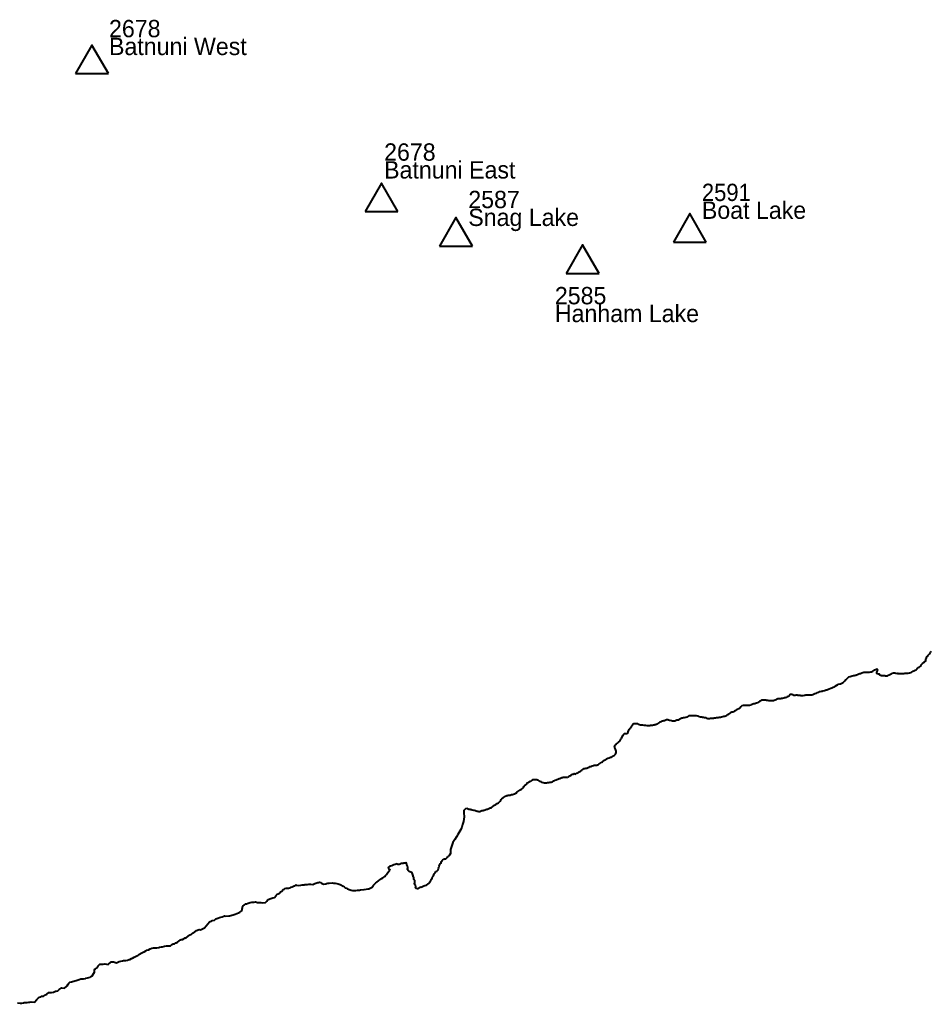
# Model space of a CAD drawing. Extents: x 322505 to 642419, y 5806860 to 5919753.
# Drawn here: x 428296 to 446724, y 5896262 to 5916133 of the extents above; entities that cross this region are included whole.
import ezdxf

# ---------------------------------------------------------------- set-up
doc = ezdxf.new("R2010")
doc.units = 0
doc.header["$LTSCALE"] = 140
doc.layers.add('1', color=7, linetype='Continuous', lineweight=40)
doc.layers.add('6', color=7, linetype='Continuous', lineweight=40)

msp = doc.modelspace()

# ---------------------------------------------------------------- linework, layer by layer
at = {"layer": '1'}
for p, q in [((429424.8, 5915042.6), (430090.1, 5915042.6)), ((435277.9, 5912255.9), (435943.2, 5912255.9)), ((441509.1, 5911637.9), (442174.5, 5911637.9)), ((436781.3, 5911557.9), (437446.7, 5911557.9)), ((439343, 5911006.9), (440008.3, 5911006.9))]:
    msp.add_line(p, q, dxfattribs=at)
for points in [[(430090.1, 5915042.6), (429757.4, 5915618.8), (429424.8, 5915042.6)], [(435943.2, 5912255.9), (435610.5, 5912832.1), (435277.9, 5912255.9)], [(442174.5, 5911637.9), (441841.8, 5912214.1), (441509.1, 5911637.9)], [(437446.7, 5911557.9), (437114, 5912134.1), (436781.3, 5911557.9)], [(440008.3, 5911006.9), (439675.7, 5911583.1), (439343, 5911006.9)]]:
    msp.add_lwpolyline(points, dxfattribs=at)
at = {"layer": '6'}
for p, q in [((433894.5, 5898647), (433881.6, 5898647.8)), ((431638, 5897581.6), (431649.8, 5897585.1)), ((429546.8, 5896754.4), (429569.2, 5896754.1))]:
    msp.add_line(p, q, dxfattribs=at)
for points in [[(445693, 5902894), (445706, 5902888), (445719, 5902886), (445732, 5902885), (445752, 5902885), (445773, 5902883), (445786, 5902882), (445800, 5902881), (445811, 5902880), (445825, 5902879), (445839, 5902881), (445860, 5902888), (445884, 5902903), (445901, 5902912), (445924, 5902925), (445933, 5902930), (445958, 5902938), (445970, 5902939), (445985, 5902937), (446008, 5902930), (446032, 5902928), (446047, 5902929), (446061, 5902928), (446077, 5902927), (446094, 5902926), (446106, 5902925), (446120, 5902926), (446144, 5902927), (446167, 5902928), (446187, 5902929), (446214, 5902929), (446228, 5902930), (446241, 5902931), (446255, 5902933), (446279, 5902938), (446291, 5902940), (446314, 5902946), (446335, 5902957), (446359, 5902969), (446372, 5902976), (446396, 5902989), (446419, 5903002), (446437, 5903021), (446446, 5903032), (446465, 5903044), (446477, 5903051), (446500, 5903064), (446507, 5903072), (446515, 5903095), (446520, 5903102), (446538, 5903121), (446545, 5903130), (446569, 5903148), (446587, 5903165), (446609, 5903181), (446609, 5903197), (446614, 5903219), (446624, 5903241), (446634, 5903261), (446650, 5903278), (446655, 5903288)], [(446655, 5903288), (446668, 5903305), (446687, 5903325), (446697, 5903339), (446705, 5903352), (446714, 5903365), (446723.5, 5903377.1)], [(444783, 5902670), (444811, 5902691), (444825, 5902699), (444849, 5902709), (444879, 5902715), (444891, 5902718), (444904, 5902723), (444926, 5902735), (444943, 5902744), (444956, 5902755), (444972, 5902779), (444991, 5902794), (445001, 5902804), (445020, 5902824), (445038, 5902839), (445059, 5902860), (445081, 5902863), (445103, 5902871), (445126, 5902878), (445150, 5902882), (445163, 5902884), (445182, 5902889), (445197, 5902893), (445212, 5902898), (445233, 5902908), (445256, 5902916), (445279, 5902922), (445294, 5902926), (445316, 5902936), (445339, 5902947), (445361, 5902953), (445373, 5902954), (445438, 5902954), (445451, 5902953), (445475, 5902955), (445500, 5902958), (445511, 5902960), (445526, 5902963), (445542, 5902970), (445560, 5902987), (445577, 5902998), (445598, 5903009), (445613, 5903015), (445623, 5903016), (445631, 5903004), (445632, 5902992), (445629, 5902979), (445623, 5902967), (445618, 5902952), (445618, 5902933), (445624, 5902927), (445633, 5902924), (445658, 5902919), (445666, 5902915), (445685, 5902899), (445693, 5902894)], [(444783, 5902670), (444782, 5902666), (444775, 5902660), (444752, 5902649), (444739, 5902643), (444724, 5902637), (444709, 5902630), (444692, 5902622), (444660, 5902610), (444644, 5902602), (444627, 5902595), (444612, 5902590), (444597, 5902586), (444582, 5902580), (444565, 5902576), (444533, 5902566), (444514, 5902562), (444498, 5902559), (444470, 5902557), (444456, 5902555), (444433, 5902544), (444410, 5902532), (444390, 5902523), (444368, 5902513), (444353, 5902506), (444330, 5902493), (444308, 5902485), (444266, 5902485), (444251, 5902486), (444209, 5902486), (444197, 5902485), (444184, 5902484), (444166, 5902480), (444151, 5902478), (444127, 5902476), (444101, 5902476), (444086, 5902477), (444073, 5902479), (444059, 5902481), (444038, 5902482), (444027, 5902482), (444013, 5902484), (443989, 5902485), (443968, 5902481), (443946, 5902482), (443930, 5902487), (443922, 5902496), (443903, 5902501), (443880, 5902501), (443868, 5902500), (443847, 5902476), (443830, 5902460), (443807, 5902451), (443787, 5902441), (443769, 5902434), (443757, 5902430), (443742, 5902426), (443718, 5902422), (443694, 5902418), (443683, 5902416), (443669, 5902415), (443642, 5902415), (443619, 5902412), (443598, 5902404), (443581, 5902393), (443570, 5902387), (443547, 5902379), (443533, 5902375), (443522, 5902374)], [(442966.4, 5902279), (442958, 5902279), (442944, 5902278), (442932, 5902279), (442917, 5902278), (442894, 5902273), (442887, 5902268), (442876, 5902249), (442862, 5902234), (442843, 5902217), (442830, 5902213), (442811, 5902201), (442809.5, 5902200.4)], [(443149.4, 5902313), (443138, 5902310), (443114, 5902302), (443101, 5902299), (443080, 5902289), (443072, 5902286), (443049, 5902281), (443036, 5902278), (443022, 5902277), (442998, 5902280), (442974, 5902279), (442967.4, 5902279)], [(443522, 5902374), (443497, 5902374), (443478, 5902373), (443450, 5902373), (443436, 5902375), (443421, 5902377), (443408, 5902379), (443395, 5902382), (443379, 5902385), (443365, 5902388), (443316, 5902388), (443292, 5902386), (443268, 5902376), (443257, 5902364), (443227, 5902344), (443208, 5902333), (443187, 5902324), (443166, 5902317), (443153, 5902314), (443149.4, 5902313)], [(442293, 5902016), (442270, 5902014), (442257, 5902013), (442242, 5902011), (442220, 5902010), (442205, 5902012), (442195, 5902014), (442175, 5902026), (442164, 5902029), (442150, 5902031), (442138, 5902031), (442121, 5902033), (442097, 5902038), (442082, 5902042), (442070, 5902043), (442057, 5902044), (442034, 5902050), (442023, 5902053), (442001, 5902060), (441979, 5902067), (441965, 5902069), (441949, 5902071), (441934, 5902071), (441918, 5902070), (441904, 5902070), (441891, 5902071), (441877, 5902073), (441856, 5902073), (441834, 5902071), (441822, 5902069), (441803, 5902056), (441783, 5902041), (441759, 5902034), (441729, 5902030), (441713, 5902028), (441692, 5902024), (441680, 5902020), (441667, 5902016), (441655, 5902010), (441640, 5902004), (441627, 5901997), (441606, 5901984), (441593, 5901982), (441579, 5901979), (441566, 5901975), (441552, 5901969), (441536, 5901963), (441515, 5901959), (441492, 5901963), (441469, 5901970), (441445, 5901974), (441432, 5901976), (441409, 5901983), (441398, 5901986), (441384, 5901988), (441371, 5901987), (441356, 5901982), (441343, 5901975), (441330, 5901971), (441317, 5901969), (441293, 5901963), (441278, 5901959), (441254, 5901951), (441233, 5901943), (441217, 5901931), (441198, 5901917), (441175, 5901902), (441159, 5901893)], [(442623.7, 5902099.3), (442607, 5902091), (442600, 5902089), (442584, 5902074), (442560, 5902062), (442549, 5902057), (442530, 5902055), (442509, 5902050), (442485, 5902043), (442461, 5902039), (442447, 5902036), (442433, 5902034), (442417, 5902032), (442395, 5902029), (442384, 5902027), (442362, 5902025), (442349, 5902023), (442334, 5902021), (442320, 5902018), (442305, 5902016), (442293, 5902016)], [(442808.7, 5902200), (442788, 5902191), (442769, 5902178), (442748, 5902162), (442726, 5902152), (442714, 5902147), (442691, 5902141), (442670, 5902134), (442649, 5902122), (442625, 5902100), (442623.7, 5902099.3)], [(440328, 5901436), (440322, 5901457), (440323, 5901462), (440334, 5901474), (440354, 5901489), (440362, 5901502), (440378, 5901517), (440402, 5901535), (440425, 5901559), (440433, 5901572), (440439, 5901585), (440449, 5901600), (440458, 5901615), (440468, 5901629), (440476, 5901642), (440482, 5901657), (440491, 5901670), (440503, 5901691), (440522, 5901712), (440533, 5901714), (440546, 5901711), (440559, 5901711), (440583, 5901720), (440593, 5901740), (440598, 5901749), (440605, 5901767), (440612, 5901782), (440618, 5901796), (440628, 5901812), (440641, 5901829), (440655, 5901845), (440672, 5901865), (440690, 5901885), (440691, 5901902), (440694, 5901910), (440709, 5901914), (440727, 5901915), (440747, 5901915), (440771, 5901918), (440780, 5901917), (440801, 5901904), (440824, 5901896), (440847, 5901890), (440860, 5901889), (440872, 5901888), (440887, 5901886), (440909, 5901883), (440922, 5901882), (440935, 5901880), (440948, 5901879), (440972, 5901876), (441006, 5901876), (441019, 5901877), (441033, 5901877), (441045, 5901879), (441060, 5901881), (441086, 5901883), (441107, 5901888), (441123, 5901891), (441136, 5901892), (441159, 5901893)], [(439393, 5900841), (439414, 5900856), (439444, 5900874), (439468, 5900893), (439490, 5900893), (439503, 5900906), (439506, 5900906), (439528, 5900894), (439537, 5900895), (439561, 5900911), (439575, 5900920), (439591, 5900930), (439606, 5900938), (439630, 5900953), (439644, 5900964), (439659, 5900974), (439678, 5900983), (439708, 5901003), (439722, 5901009), (439739, 5901013), (439757, 5901014), (439774, 5901018), (439790, 5901025), (439805, 5901031), (439829, 5901043), (439841, 5901048), (439855, 5901053), (439868, 5901058), (439893, 5901065), (439906, 5901071), (439919, 5901075), (439934, 5901074), (439949, 5901072), (439964, 5901072), (439978, 5901077), (439993, 5901086), (440005, 5901096), (440024, 5901107), (440045, 5901119), (440066, 5901132), (440080, 5901142), (440093, 5901153), (440115, 5901174), (440128, 5901182), (440141, 5901189), (440156, 5901198), (440170, 5901208), (440183, 5901215), (440210, 5901224), (440240, 5901232), (440253, 5901237), (440266, 5901244), (440282, 5901252), (440310, 5901270), (440325, 5901282), (440337, 5901295), (440345, 5901308), (440350, 5901329), (440352, 5901340), (440351, 5901355), (440344, 5901379), (440335, 5901399), (440330, 5901410), (440328, 5901425), (440328, 5901436)], [(439393, 5900841), (439377, 5900831), (439367, 5900826), (439343, 5900825), (439309, 5900825), (439296, 5900823), (439280, 5900821), (439268, 5900819), (439255, 5900816), (439243, 5900812), (439229, 5900806), (439216, 5900800), (439203, 5900797), (439188, 5900791), (439175, 5900785), (439151, 5900777), (439138, 5900773), (439116, 5900763), (439105, 5900757), (439088, 5900749), (439074, 5900741), (439061, 5900732), (439042, 5900723), (439009, 5900720), (438990, 5900719), (438979, 5900717), (438965, 5900714), (438943, 5900711), (438927, 5900710), (438902, 5900710), (438880, 5900719), (438860, 5900726), (438839, 5900735), (438816, 5900743), (438799, 5900754), (438777, 5900767), (438764, 5900772), (438750, 5900775), (438688, 5900775), (438671, 5900776), (438653, 5900772), (438633, 5900759), (438612, 5900744), (438591, 5900732), (438568, 5900716), (438557, 5900708), (438543, 5900690), (438521, 5900679)], [(438464.9, 5900606), (438479, 5900625), (438487, 5900644), (438506, 5900667), (438521, 5900679)], [(437346, 5900196), (437364, 5900190), (437374, 5900186), (437389, 5900183), (437403, 5900182), (437415, 5900180), (437428, 5900175), (437442, 5900171), (437469, 5900165), (437485, 5900161), (437508, 5900155), (437526, 5900150), (437542, 5900147), (437560, 5900142), (437574, 5900139), (437597, 5900140), (437610, 5900145), (437635, 5900155), (437648, 5900157), (437663, 5900158), (437677, 5900161), (437688, 5900164), (437705, 5900169), (437720, 5900175), (437737, 5900182), (437754, 5900187), (437778, 5900197), (437791, 5900202), (437806, 5900209), (437820, 5900214), (437832, 5900218), (437854, 5900234), (437868, 5900244), (437892, 5900262), (437905, 5900270), (437920, 5900280), (437950, 5900298), (437974, 5900314), (437998, 5900335), (438010, 5900349), (438021, 5900363), (438031, 5900377), (438044, 5900392), (438068, 5900413), (438079, 5900422), (438099, 5900436), (438118, 5900450), (438142, 5900458), (438154, 5900461), (438168, 5900464), (438181, 5900466), (438196, 5900468), (438208, 5900469), (438222, 5900471), (438240, 5900479), (438261, 5900482), (438277, 5900486), (438296, 5900492), (438308.8, 5900499.6)], [(438308.8, 5900499.6), (438318, 5900505), (438329, 5900510), (438348, 5900528), (438365, 5900542), (438385, 5900555), (438407, 5900569), (438416, 5900575), (438438, 5900586), (438462, 5900602), (438464.7, 5900605.7)], [(437346, 5900196), (437310.7, 5900188.1), (437275.1, 5900155.7), (437271.9, 5900113.5), (437278.3, 5900026), (437265.4, 5899938.4), (437249.2, 5899876.8), (437236.2, 5899821.7), (437210.3, 5899773.1), (437155.2, 5899675.8), (437126, 5899627.2), (437093.6, 5899572), (437051.5, 5899510.5), (437006.1, 5899367.8), (437002.8, 5899348.3), (437002.8, 5899338.6), (437001.8, 5899290.1), (436986.7, 5899251.9), (436961, 5899227)], [(436294.3, 5898641.1), (436279, 5898668), (436277, 5898677), (436281, 5898699), (436282, 5898710), (436282, 5898734), (436266, 5898766), (436266, 5898777), (436262, 5898797), (436252, 5898819), (436248, 5898840), (436244, 5898855), (436239, 5898879), (436233, 5898897), (436223, 5898904), (436202, 5898912), (436182, 5898918), (436170, 5898924), (436151, 5898944), (436137, 5898963), (436136, 5898970), (436140, 5898995), (436140, 5899008), (436139, 5899024), (436136, 5899036), (436125, 5899058), (436119, 5899080), (436115, 5899090), (436116, 5899096), (436105, 5899098), (436085, 5899093), (436063, 5899091), (436049, 5899090), (436026, 5899088), (436002, 5899084), (435989, 5899074), (435968, 5899067), (435946, 5899068), (435926, 5899077), (435906, 5899075), (435884, 5899066), (435861, 5899058), (435848, 5899054), (435835, 5899049), (435816, 5899039), (435795, 5899031), (435772, 5899024), (435752, 5899012), (435747, 5899005), (435750, 5898991), (435766, 5898973), (435776, 5898963), (435776, 5898959)], [(436413, 5898606), (436426, 5898618), (436451, 5898632), (436466, 5898636), (436488, 5898640), (436516, 5898648), (436528, 5898654), (436549, 5898670), (436571, 5898688), (436586, 5898705), (436589, 5898717), (436605, 5898741), (436612, 5898754), (436620, 5898769), (436631, 5898793), (436644, 5898817), (436658, 5898838), (436666, 5898861), (436675, 5898875), (436693, 5898895), (436702, 5898914), (436711, 5898924), (436725, 5898930), (436747, 5898951), (436754, 5898961), (436761, 5898983), (436768, 5899005), (436778, 5899035), (436783, 5899056), (436794, 5899079), (436813, 5899093), (436818, 5899115), (436822, 5899127), (436836, 5899145), (436852, 5899158), (436872, 5899174), (436886, 5899179), (436909, 5899184), (436925, 5899196), (436942, 5899215), (436954, 5899225), (436961, 5899227)], [(433881.6, 5898647.8), (433942.3, 5898639.9), (433981, 5898652), (434008, 5898655), (434021, 5898654), (434037, 5898656), (434048, 5898656), (434061, 5898660), (434086, 5898665), (434113, 5898663), (434139, 5898666), (434166, 5898666), (434179, 5898669), (434179, 5898669), (434223.8, 5898665.4), (434249, 5898678), (434265, 5898684), (434323, 5898700), (434336, 5898705), (434360, 5898709), (434360, 5898709), (434379, 5898704), (434379, 5898704), (434398, 5898692), (434440.7, 5898671.6), (434487, 5898679), (434500, 5898683), (434523, 5898687), (434542, 5898689), (434554, 5898692), (434554, 5898692), (434614, 5898693), (434637, 5898692), (434671, 5898692), (434708, 5898685), (434731, 5898677), (434754, 5898672), (434772, 5898665), (434772, 5898665), (434772, 5898665), (434772, 5898665), (434788, 5898658), (434835, 5898632), (434853, 5898615), (434877, 5898598), (434901, 5898590), (434925, 5898576), (434955, 5898563), (434998, 5898547), (435022, 5898541), (435047, 5898539), (435068, 5898540), (435092, 5898543), (435128, 5898545), (435163, 5898548), (435188, 5898553), (435257, 5898564), (435303, 5898568), (435338, 5898574), (435357, 5898576), (435418.2, 5898606.1), (435451, 5898651), (435459, 5898660), (435477, 5898678), (435497, 5898693), (435515, 5898712), (435582, 5898762), (435605, 5898775), (435634, 5898796), (435657, 5898809), (435676, 5898825), (435688, 5898843), (435712, 5898867), (435727, 5898885), (435776, 5898959)], [(431649.8, 5897585.1), (431666, 5897591), (431730, 5897641), (431739, 5897646), (431772, 5897660), (431792, 5897676), (431834, 5897705), (431868, 5897730), (431868, 5897730), (431923, 5897751), (431923, 5897751), (431923, 5897751), (431949.9, 5897746.7), (431990, 5897765), (432034.7, 5897787.9), (432134, 5897905), (432134, 5897905), (432150, 5897917), (432150, 5897917), (432167, 5897921), (432176, 5897927), (432188, 5897932), (432188, 5897932), (432236.2, 5897940), (432261, 5897971), (432261, 5897971), (432261, 5897971), (432304, 5897980), (432336, 5897993), (432389, 5898010), (432425, 5898025), (432437, 5898028), (432437, 5898028), (432465, 5898024), (432521, 5898027), (432538, 5898027), (432612, 5898047), (432651, 5898060), (432718, 5898088), (432733, 5898096), (432747, 5898104), (432785.4, 5898132.8), (432797, 5898196), (432801, 5898206), (432816, 5898231), (432835, 5898248), (432871, 5898270), (432871, 5898270), (432881, 5898273), (432917, 5898287), (432957, 5898299), (432986, 5898304), (433004, 5898306), (433037, 5898307), (433062, 5898309), (433062, 5898309), (433106, 5898302), (433122, 5898298), (433146, 5898296), (433171, 5898299), (433207, 5898293), (433265.8, 5898295.9), (433291, 5898327), (433308, 5898344), (433328, 5898358), (433356, 5898372), (433390, 5898383), (433414, 5898392), (433449.1, 5898402.2), (433478, 5898439), (433491, 5898457), (433502, 5898465), (433518, 5898475), (433550.6, 5898489.7), (433567, 5898516), (433595.8, 5898530.4), (433622, 5898559), (433640, 5898571), (433659, 5898582), (433680, 5898587), (433737.3, 5898587), (433764, 5898597), (433782, 5898607), (433804, 5898617), (433828, 5898631), (433842, 5898636), (433856, 5898638), (433879, 5898647), (433879, 5898647), (433894.5, 5898647)], [(436413, 5898606), (436391, 5898601), (436367, 5898590), (436348, 5898577), (436338, 5898575), (436313, 5898582), (436303, 5898586), (436298, 5898593), (436302, 5898616), (436294.3, 5898641.1)], [(429569.2, 5896754.1), (429588, 5896756), (429624, 5896765), (429635, 5896768), (429667, 5896779), (429719.6, 5896791.7), (429737, 5896807), (429737, 5896807), (429760.2, 5896817.5), (429807.5, 5896893.3), (429807, 5896932), (429807, 5896932), (429814, 5896949), (429814, 5896949), (429814, 5896949), (429830, 5896961), (429849, 5896973), (429872, 5896996), (429884, 5897021), (429897, 5897036), (429916, 5897051), (429916, 5897051), (429922, 5897053), (429936, 5897054), (429936, 5897054), (429955, 5897051), (429985, 5897053), (430019, 5897059), (430087, 5897048.5), (430137, 5897093), (430146, 5897098), (430157, 5897099), (430176, 5897099), (430194, 5897098), (430194, 5897098), (430255.4, 5897079.7), (430291, 5897103), (430291, 5897103), (430306, 5897108), (430378, 5897123), (430395.2, 5897124), (430444, 5897127), (430477, 5897134), (430508, 5897145), (430521, 5897150), (430555, 5897167), (430578, 5897176), (430610, 5897194), (430667, 5897219), (430688, 5897231), (430705, 5897246), (430767, 5897279), (430795, 5897293), (430811, 5897300), (430846, 5897325), (430846, 5897325), (430868, 5897334), (430901, 5897345), (430935, 5897363), (430971, 5897378), (431001, 5897383), (431015, 5897382), (431028, 5897380), (431044, 5897380), (431070, 5897384), (431107, 5897393), (431120, 5897394), (431160, 5897404), (431175, 5897406), (431221, 5897415), (431264, 5897421), (431277, 5897422), (431344.9, 5897422), (431372, 5897448), (431372, 5897448), (431397, 5897461), (431397, 5897461), (431423, 5897467), (431447, 5897481), (431457, 5897486), (431489, 5897500), (431511, 5897518), (431549, 5897546), (431561, 5897550), (431561, 5897550), (431586.8, 5897552.6), (431624, 5897574), (431644, 5897583), (431644, 5897583), (431638, 5897581.6)], [(428250, 5896273), (428304, 5896262), (428319, 5896262), (428338, 5896263), (428375, 5896274), (428385, 5896276), (428403, 5896278), (428440, 5896278), (428451, 5896279), (428480, 5896285), (428504, 5896286), (428530, 5896289), (428599.1, 5896287.4), (428640, 5896342), (428678, 5896376), (428678, 5896376), (428694, 5896385), (428724, 5896396), (428742, 5896406), (428777.9, 5896409.3), (428820, 5896435), (428844, 5896446), (428888, 5896481), (428888, 5896481), (428899, 5896483), (428938, 5896483), (428980, 5896489), (429018, 5896505), (429035, 5896511), (429067, 5896517), (429096, 5896544), (429132, 5896567), (429142, 5896572), (429149, 5896573), (429149, 5896573), (429201.1, 5896568.3), (429241, 5896604), (429254, 5896618), (429274, 5896647), (429288, 5896672), (429288, 5896672), (429308, 5896690), (429308, 5896690), (429345, 5896698), (429363, 5896703), (429440, 5896721), (429460, 5896731), (429496, 5896745), (429534, 5896756), (429534, 5896756), (429546.8, 5896754.4)]]:
    msp.add_lwpolyline(points, dxfattribs=at)

# ---------------------------------------------------------------- texts
at = {"layer": '1'}
for s, p in [('2678', (430102.3, 5915777.6)), ('Batnuni West', (430102.3, 5915417.6)), ('2678', (435662.7, 5913284.1)), ('Batnuni East', (435662.7, 5912924.1)), ('2587', (437364.4, 5912325.1)), ('Boat Lake', (442085.9, 5912109)), ('Snag Lake', (437364.4, 5911965.1)), ('2585', (439114, 5910383.1)), ('Hanham Lake', (439114, 5910023.1))]:
    msp.add_text(s, height=350, dxfattribs=at).set_placement(p)
at = {"layer": '1', "width": 0.95}
msp.add_text('2591', height=350, dxfattribs=at).set_placement((442085.9, 5912469))

doc.saveas('drawing.dxf')
